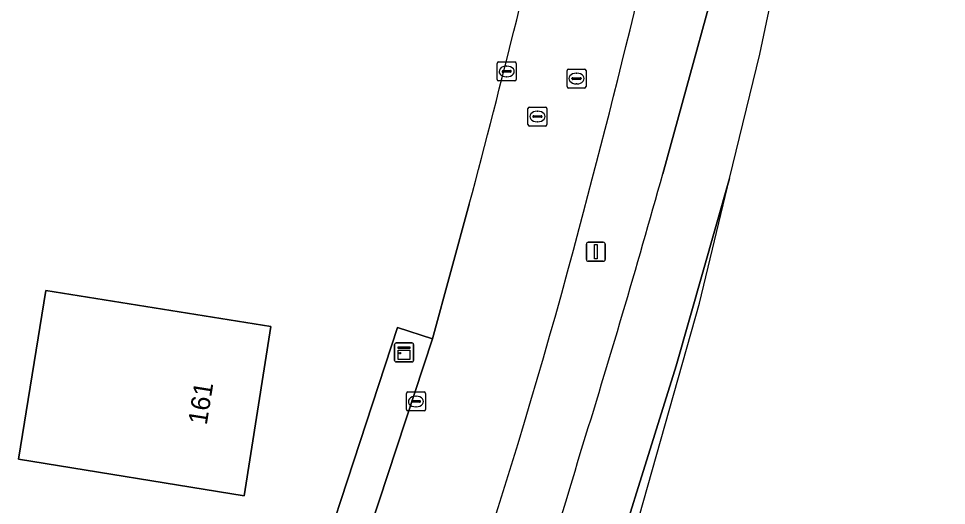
# Model space of a CAD drawing. Extents: x 154324 to 155744, y 382937 to 384188.
# Drawn here: x 155344.29 to 155393.14, y 383238.64 to 383264.28 of the extents above; entities that cross this region are included whole.
import ezdxf

# ---------------------------------------------------------------- set-up
doc = ezdxf.new("R2010")
doc.units = 0
for name, color, linetype in [('IMGEO_Berm_groen', 7, 'Continuous'), ('IMGEO_Erf', 7, 'Continuous'), ('IMGEO_Fietspad_gesloten', 7, 'Continuous'), ('IMGEO_Groenvoorziening', 7, 'Continuous'), ('IMGEO_Kast', 7, 'Continuous'), ('IMGEO_Kolk', 7, 'Continuous'), ('IMGEO_Lichtmast', 7, 'Continuous'), ('IMGEO_Pand', 7, 'Continuous'), ('IMGEO_Pand_nummerreeks', 7, 'Continuous'), ('IMGEO_Rijbaan_lokaal_gesloten', 7, 'Continuous'), ('IMGEO_Rioolput', 7, 'Continuous'), ('IMGEO_Voetpad_open', 7, 'Continuous')]:
    doc.layers.add(name, color=color, linetype=linetype)

msp = doc.modelspace()

# ---------------------------------------------------------------- linework, layer by layer
at = {"layer": 'IMGEO_Berm_groen'}
msp.add_lwpolyline([(155378.211, 383256.107), (155382.092, 383270.232), (155385.619, 383284.035)], dxfattribs=at)
for centre, radius, start, end in [((154920.161, 383375.05), 469.711, 344.96734, 348.48239), ((154859.102, 383401.381), 539.053, 342.73246, 344.36555), ((155088.644, 383327.943), 294.78, 338.00066, 345.31634), ((155146.238, 383308.495), 237.313, 339.84457, 343.56976)]:
    msp.add_arc(centre, radius, start, end, dxfattribs=at)
at = {"layer": 'IMGEO_Erf'}
msp.add_lwpolyline([(155357.974, 383228.876), (155364.232, 383248.015), (155366.082, 383247.416), (155368.018, 383254.513)], dxfattribs=at)
msp.add_lwpolyline([(155357.573, 383248.067), (155356.157, 383239.149), (155344.285, 383241.069), (155345.717, 383249.958)], close=True, dxfattribs=at)
msp.add_arc((154771.317, 383413.289), 617.464, 345.099417, 346.959795, dxfattribs=at)
at = {"layer": 'IMGEO_Fietspad_gesloten'}
for points in [[(155374.508, 383231.879), (155378.906, 383245.985), (155381.726, 383255.864), (155383.313, 383262.405), (155386.611, 383278.083), (155388.426, 383286.714), (155391.127, 383303.306), (155393.141, 383320.278)], [(155385.619, 383284.035), (155382.092, 383270.232), (155378.211, 383256.107)]]:
    msp.add_lwpolyline(points, dxfattribs=at)
for centre, radius, start, end in [((154859.102, 383401.381), 539.053, 342.73246, 344.36555), ((155146.238, 383308.495), 237.313, 339.84457, 343.56976)]:
    msp.add_arc(centre, radius, start, end, dxfattribs=at)
at = {"layer": 'IMGEO_Groenvoorziening'}
msp.add_lwpolyline([(155365.231, 383208.265), (155369.133, 383216.585), (155373.763, 383227.389), (155376.061, 383234.88), (155380.13, 383249.286), (155381.726, 383255.864), (155378.906, 383245.985), (155374.508, 383231.879)], dxfattribs=at)
at = {"layer": 'IMGEO_Kast'}
for p, q in [((155364.086, 383246.27), (155364.086, 383247.111)), ((155364.086, 383247.111), (155364.086, 383246.27)), ((155364.161, 383247.195), (155365.002, 383247.195)), ((155365.002, 383247.195), (155364.161, 383247.195)), ((155365.086, 383247.12), (155365.086, 383246.279)), ((155365.086, 383246.279), (155365.086, 383247.12)), ((155365.011, 383246.195), (155364.17, 383246.195)), ((155364.17, 383246.195), (155365.011, 383246.195))]:
    msp.add_line(p, q, dxfattribs=at)
for points in [[(155364.281, 383246.985), (155364.881, 383246.985), (155364.881, 383246.9), (155364.281, 383246.9), (155364.281, 383246.985)], [(155364.281, 383246.81), (155364.881, 383246.81), (155364.881, 383246.321), (155364.281, 383246.321), (155364.281, 383246.81)]]:
    msp.add_lwpolyline(points, dxfattribs=at)
msp.add_circle((155364.365, 383246.659), 0.0377, dxfattribs=at)
for centre, start, end in [((155364.164, 383247.117), 92.4484, 184.2845), ((155364.164, 383247.117), 92.4484, 184.2845), ((155365.008, 383247.117), 2.4484, 94.2845), ((155365.008, 383247.117), 2.4484, 94.2845), ((155364.164, 383246.273), 182.4484, 274.2845), ((155364.164, 383246.273), 182.4484, 274.2845), ((155365.008, 383246.273), 272.4484, 4.2845), ((155365.008, 383246.273), 272.4484, 4.2845)]:
    msp.add_arc(centre, 0.0779, start, end, dxfattribs=at)
at = {"layer": 'IMGEO_Kolk'}
for p, q in [((155369.486, 383261.069), (155369.486, 383261.921)), ((155369.561, 383261.995), (155370.413, 383261.995)), ((155369.974, 383261.775), (155369.999, 383261.775)), ((155370.487, 383261.921), (155370.487, 383261.069)), ((155369.745, 383261.489), (155369.745, 383261.501)), ((155370.183, 383261.452), (155369.785, 383261.452)), ((155369.788, 383261.538), (155370.186, 383261.538)), ((155370.229, 383261.501), (155370.229, 383261.489)), ((155370.413, 383260.995), (155369.561, 383260.995)), ((155369.997, 383261.215), (155369.972, 383261.215)), ((155364.708, 383243.689), (155364.708, 383244.541)), ((155364.783, 383244.615), (155365.635, 383244.615)), ((155365.01, 383244.158), (155365.408, 383244.158)), ((155365.196, 383244.395), (155365.221, 383244.395)), ((155365.709, 383244.541), (155365.709, 383243.689)), ((155364.967, 383244.109), (155364.967, 383244.121)), ((155365.405, 383244.072), (155365.007, 383244.072)), ((155365.219, 383243.835), (155365.194, 383243.835)), ((155365.451, 383244.121), (155365.451, 383244.109)), ((155365.635, 383243.615), (155364.783, 383243.615))]:
    msp.add_line(p, q, dxfattribs=at)
for points in [[(155369.486, 383261.069), (155369.486, 383261.921)], [(155369.561, 383261.995), (155370.413, 383261.995)], [(155370.487, 383261.921), (155370.487, 383261.069)], [(155370.413, 383260.995), (155369.561, 383260.995)], [(155364.708, 383243.689), (155364.708, 383244.541)], [(155364.783, 383244.615), (155365.635, 383244.615)], [(155365.709, 383244.541), (155365.709, 383243.689)], [(155365.635, 383243.615), (155364.783, 383243.615)]]:
    msp.add_lwpolyline(points, dxfattribs=at)
for centre, radius, start, end in [((155369.563, 383261.919), 0.0765, 91.552, 178.448), ((155369.563, 383261.919), 0.0765, 91.552, 178.448), ((155370.411, 383261.919), 0.0765, 1.552, 88.448), ((155370.411, 383261.919), 0.0765, 1.552, 88.448), ((155369.785, 383261.498), 0.0403, 85.8775, 175.7526), ((155369.782, 383261.488), 0.0366, 178.938, 274.7102), ((155370.186, 383261.495), 0.043, 264.8664, 352.4533), ((155370.19, 383261.5), 0.0386, 1.7309, 96.639), ((155369.563, 383261.071), 0.0765, 181.552, 268.448), ((155369.563, 383261.071), 0.0765, 181.552, 268.448), ((155370.411, 383261.071), 0.0765, 271.552, 358.448), ((155370.411, 383261.071), 0.0765, 271.552, 358.448), ((155364.785, 383244.539), 0.0765, 91.552, 178.448), ((155364.785, 383244.539), 0.0765, 91.552, 178.448), ((155365.007, 383244.118), 0.0403, 85.8775, 175.7526), ((155365.412, 383244.12), 0.0386, 1.7309, 96.639), ((155365.633, 383244.539), 0.0765, 1.552, 88.448), ((155365.633, 383244.539), 0.0765, 1.552, 88.448), ((155364.785, 383243.691), 0.0765, 181.552, 268.448), ((155364.785, 383243.691), 0.0765, 181.552, 268.448), ((155365.004, 383244.108), 0.0366, 178.938, 274.7102), ((155365.408, 383244.115), 0.043, 264.8664, 352.4533), ((155365.633, 383243.691), 0.0765, 271.552, 358.448), ((155365.633, 383243.691), 0.0765, 271.552, 358.448)]:
    msp.add_arc(centre, radius, start, end, dxfattribs=at)
for centre, major_axis, ratio, start_param, end_param in [((155369.973, 383261.495), (-0.387, 0.002), 0.722429, 4.712389, 7.853982), ((155369.998, 383261.495), (-0.39, 0.002), 0.717154, 1.570796, 4.712389), ((155365.195, 383244.115), (-0.387, 0.002), 0.722429, 4.712389, 7.853982), ((155365.22, 383244.115), (-0.39, 0.002), 0.717154, 1.570796, 4.712389)]:
    msp.add_ellipse(centre, major_axis=major_axis, ratio=ratio, start_param=start_param, end_param=end_param, dxfattribs=at)
at = {"layer": 'IMGEO_Lichtmast'}
for p, q in [((155374.283, 383252.5), (155375.073, 383252.5)), ((155375.073, 383252.5), (155374.283, 383252.5)), ((155374.183, 383251.6), (155374.183, 383252.4)), ((155374.183, 383252.4), (155374.183, 383251.6)), ((155375.173, 383252.4), (155375.173, 383251.6)), ((155375.173, 383251.6), (155375.173, 383252.4)), ((155375.073, 383251.5), (155374.283, 383251.5)), ((155374.283, 383251.5), (155375.073, 383251.5))]:
    msp.add_line(p, q, dxfattribs=at)
msp.add_lwpolyline([(155374.603, 383252.375), (155374.753, 383252.375), (155374.753, 383251.625), (155374.603, 383251.625), (155374.603, 383252.375)], dxfattribs=at)
for centre, start, end in [((155374.283, 383252.4), 90, 180), ((155374.283, 383252.4), 90, 180), ((155375.073, 383252.4), 0, 90), ((155375.073, 383252.4), 360, 90), ((155374.283, 383251.6), 180, 270), ((155374.283, 383251.6), 180, 270), ((155375.073, 383251.6), 270, 0), ((155375.073, 383251.6), 270, 0)]:
    msp.add_arc(centre, 0.1, start, end, dxfattribs=at)
at = {"layer": 'IMGEO_Pand'}
msp.add_lwpolyline([(155357.573, 383248.067), (155345.717, 383249.958), (155344.285, 383241.069), (155356.157, 383239.149)], close=True, dxfattribs=at)
at = {"layer": 'IMGEO_Rijbaan_lokaal_gesloten'}
msp.add_lwpolyline([(155368.018, 383254.513), (155366.082, 383247.416), (155359.493, 383227.412)], dxfattribs=at)
for centre, radius, start, end in [((154920.161, 383375.05), 469.711, 344.96734, 348.48239), ((154771.317, 383413.289), 617.464, 345.099417, 346.959795), ((155088.644, 383327.943), 294.78, 338.00066, 345.31634)]:
    msp.add_arc(centre, radius, start, end, dxfattribs=at)
at = {"layer": 'IMGEO_Rioolput'}
for p, q in [((155373.164, 383260.695), (155373.164, 383261.547)), ((155373.239, 383261.621), (155374.091, 383261.621)), ((155373.652, 383261.401), (155373.677, 383261.401)), ((155374.165, 383261.547), (155374.165, 383260.695)), ((155373.423, 383261.115), (155373.423, 383261.127)), ((155373.861, 383261.078), (155373.463, 383261.078)), ((155373.466, 383261.164), (155373.864, 383261.164)), ((155373.675, 383260.841), (155373.65, 383260.841)), ((155373.907, 383261.127), (155373.907, 383261.115)), ((155374.091, 383260.621), (155373.239, 383260.621)), ((155371.106, 383258.696), (155371.106, 383259.548)), ((155371.181, 383259.622), (155372.033, 383259.622)), ((155371.594, 383259.402), (155371.619, 383259.402)), ((155372.107, 383259.548), (155372.107, 383258.696)), ((155371.365, 383259.116), (155371.365, 383259.128)), ((155371.803, 383259.079), (155371.405, 383259.079)), ((155371.408, 383259.165), (155371.806, 383259.165)), ((155371.617, 383258.842), (155371.592, 383258.842)), ((155371.849, 383259.128), (155371.849, 383259.116)), ((155372.033, 383258.622), (155371.181, 383258.622))]:
    msp.add_line(p, q, dxfattribs=at)
for points in [[(155373.164, 383260.695), (155373.164, 383261.547)], [(155373.239, 383261.621), (155374.091, 383261.621)], [(155374.165, 383261.547), (155374.165, 383260.695)], [(155374.091, 383260.621), (155373.239, 383260.621)], [(155371.106, 383258.696), (155371.106, 383259.548)], [(155371.181, 383259.622), (155372.033, 383259.622)], [(155372.107, 383259.548), (155372.107, 383258.696)], [(155372.033, 383258.622), (155371.181, 383258.622)]]:
    msp.add_lwpolyline(points, dxfattribs=at)
for centre, radius, start, end in [((155373.241, 383261.545), 0.0765, 91.552, 178.448), ((155373.241, 383261.545), 0.0765, 91.552, 178.448), ((155374.089, 383261.545), 0.0765, 1.552, 88.448), ((155374.089, 383261.545), 0.0765, 1.552, 88.448), ((155373.463, 383261.124), 0.0403, 85.8775, 175.7526), ((155373.46, 383261.114), 0.0366, 178.938, 274.7102), ((155373.864, 383261.121), 0.043, 264.8664, 352.4533), ((155373.868, 383261.126), 0.0386, 1.7309, 96.639), ((155373.241, 383260.697), 0.0765, 181.552, 268.448), ((155373.241, 383260.697), 0.0765, 181.552, 268.448), ((155374.089, 383260.697), 0.0765, 271.552, 358.448), ((155374.089, 383260.697), 0.0765, 271.552, 358.448), ((155371.183, 383259.546), 0.0765, 91.552, 178.448), ((155371.183, 383259.546), 0.0765, 91.552, 178.448), ((155372.031, 383259.546), 0.0765, 1.552, 88.448), ((155372.031, 383259.546), 0.0765, 1.552, 88.448), ((155371.405, 383259.125), 0.0403, 85.8775, 175.7526), ((155371.402, 383259.115), 0.0366, 178.938, 274.7102), ((155371.806, 383259.122), 0.043, 264.8664, 352.4533), ((155371.81, 383259.127), 0.0386, 1.7309, 96.639), ((155371.183, 383258.698), 0.0765, 181.552, 268.448), ((155371.183, 383258.698), 0.0765, 181.552, 268.448), ((155372.031, 383258.698), 0.0765, 271.552, 358.448), ((155372.031, 383258.698), 0.0765, 271.552, 358.448)]:
    msp.add_arc(centre, radius, start, end, dxfattribs=at)
for centre, major_axis, ratio, start_param, end_param in [((155373.651, 383261.121), (-0.387, 0.002), 0.722429, 4.712389, 7.853982), ((155373.676, 383261.121), (-0.39, 0.002), 0.717154, 1.570796, 4.712389), ((155371.593, 383259.122), (-0.387, 0.002), 0.722429, 4.712389, 7.853982), ((155371.618, 383259.122), (-0.39, 0.002), 0.717154, 1.570796, 4.712389)]:
    msp.add_ellipse(centre, major_axis=major_axis, ratio=ratio, start_param=start_param, end_param=end_param, dxfattribs=at)
at = {"layer": 'IMGEO_Voetpad_open'}
msp.add_lwpolyline([(155359.493, 383227.412), (155366.082, 383247.416), (155364.232, 383248.015), (155357.974, 383228.876)], dxfattribs=at)

# ---------------------------------------------------------------- texts
at = {"layer": 'IMGEO_Pand_nummerreeks'}
msp.add_text('161', height=1, rotation=80.9785, dxfattribs=at).set_placement((155354.192, 383242.844))

doc.saveas('drawing.dxf')
